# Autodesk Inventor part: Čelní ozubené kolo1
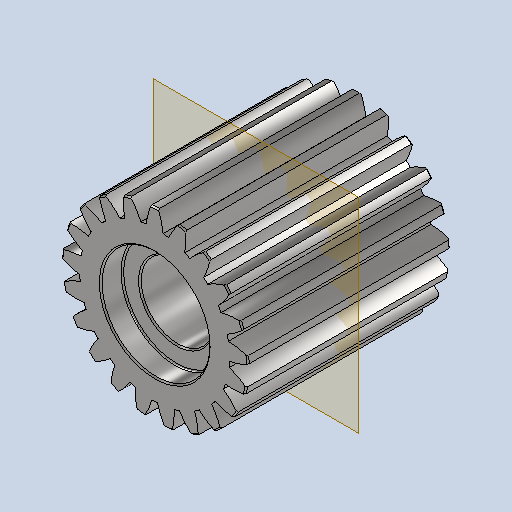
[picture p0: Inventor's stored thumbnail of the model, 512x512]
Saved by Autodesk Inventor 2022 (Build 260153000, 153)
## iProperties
CustomPartVersion: 1
Created: 2025-05
Part Number: Čelní ozubené kolo1
Material: Nerezová ocel
Document SubType Name: Modeling
Designer: jbart
Categories: <?xml version="1.0" encoding="UTF-16"?> <MemberInstance><Categories><FamilyTemplate><FamilyTemplateParameter ValueType="xs:double" Id="1" ObjectReferenceKey="da
Density: 8 g/cm^3
Appearance: Pololeštěná
Mass: 11389.5 g
Surface Area: 1668.6 cm^2
Volume: 1423.69 cm^3
Author: jbart
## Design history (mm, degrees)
sketch "Sketch1"
  geometry: C1 r 68.996 at (0, 0)
  constraints: 1 centre point
  dimensions: "d0" = 137.99216 diameter of C1 (= da_da)
extrude "Extrusion1" new body sketch "Sketch1" distance "d1" = 150 (= da_b); taper "d2" = 0 deg
workplane "Work Plane2"
sketch "Sketch2"
  geometry: C1 r 68.996 at (0, 0) reference; C2 r 63 at (0, 0)
  constraints: 1 centre point, 1 coincident
  dimensions: "d3" = 126 diameter of C2 (= da_d)
feature "Roztečný průměr" sketch "Sketch2" dims "d4" = 10, "d5" = 0
workplane "Work Plane8"
workplane "Work Plane9"
feature "Čelní ozubené kolo" dims "da_b" = 150, "da_d" = 126, "da_aw" = 366.61846, "da_da" = 137.99216, "da_df" = 111, "da_dw" = 126.21291, angle "da_beta" = 0 deg, "da_lefttooth" = 0, "da_righttooth" = 0
sketch "Náčrt3"
  geometry: C1 r 40 at (0, 0); 1 further point
  constraints: 1 centre point, 1 coincident
  dimensions: "d49" = 80 diameter of C1
extrude "Vysunutí2" cut sketch "Náčrt3" distance "d50" = 16; taper "d51" = 0 deg
fillet "Zaoblení1" dims "d52" = 1
chamfer "Zkosení1" distance "d53" = 1; stored, may be unused: second distance "d54" = 2, angle "d55" = 45 deg
sketch "Náčrt4"
  geometry: C1 r 27 at (0, 0); 1 further point
  constraints: 1 centre point, 1 coincident
  dimensions: "d56" = 54 diameter of C1
node "Pracovní rovina11"
extrude "Vysunutí4" cut sketch "Náčrt4" extent not by distance; stored distance "d63" = 0; taper "d64" = 0 deg
mirror "Zrcadlit2"
fillet "Zaoblení2" dims "d65" = 1
chamfer "Zkosení3" distance "d66" = 1; stored, may be unused: second distance "d67" = 2, angle "d68" = 45 deg
chamfer "Zkosení4" distance "d69" = 1; stored, may be unused: second distance "d70" = 2, angle "d71" = 45 deg
chamfer "Zkosení5" distance "d72" = 1; stored, may be unused: second distance "d73" = 2, angle "d74" = 45 deg
body "Solid1"
body "Srf1"
other parameters: "d16" = 366.61846 (= da_aw), "d17" = 0, "d34" = 1.496 (computed from da_z), "d39" = 0, "d41" = 0, "d43" = 366.61846 (= da_aw), "d46" = 366.61846 (= da_aw), "d47" = 0, "d48" = 0, "d62" = -75
